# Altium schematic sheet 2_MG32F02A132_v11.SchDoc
size 381 x 241 mm
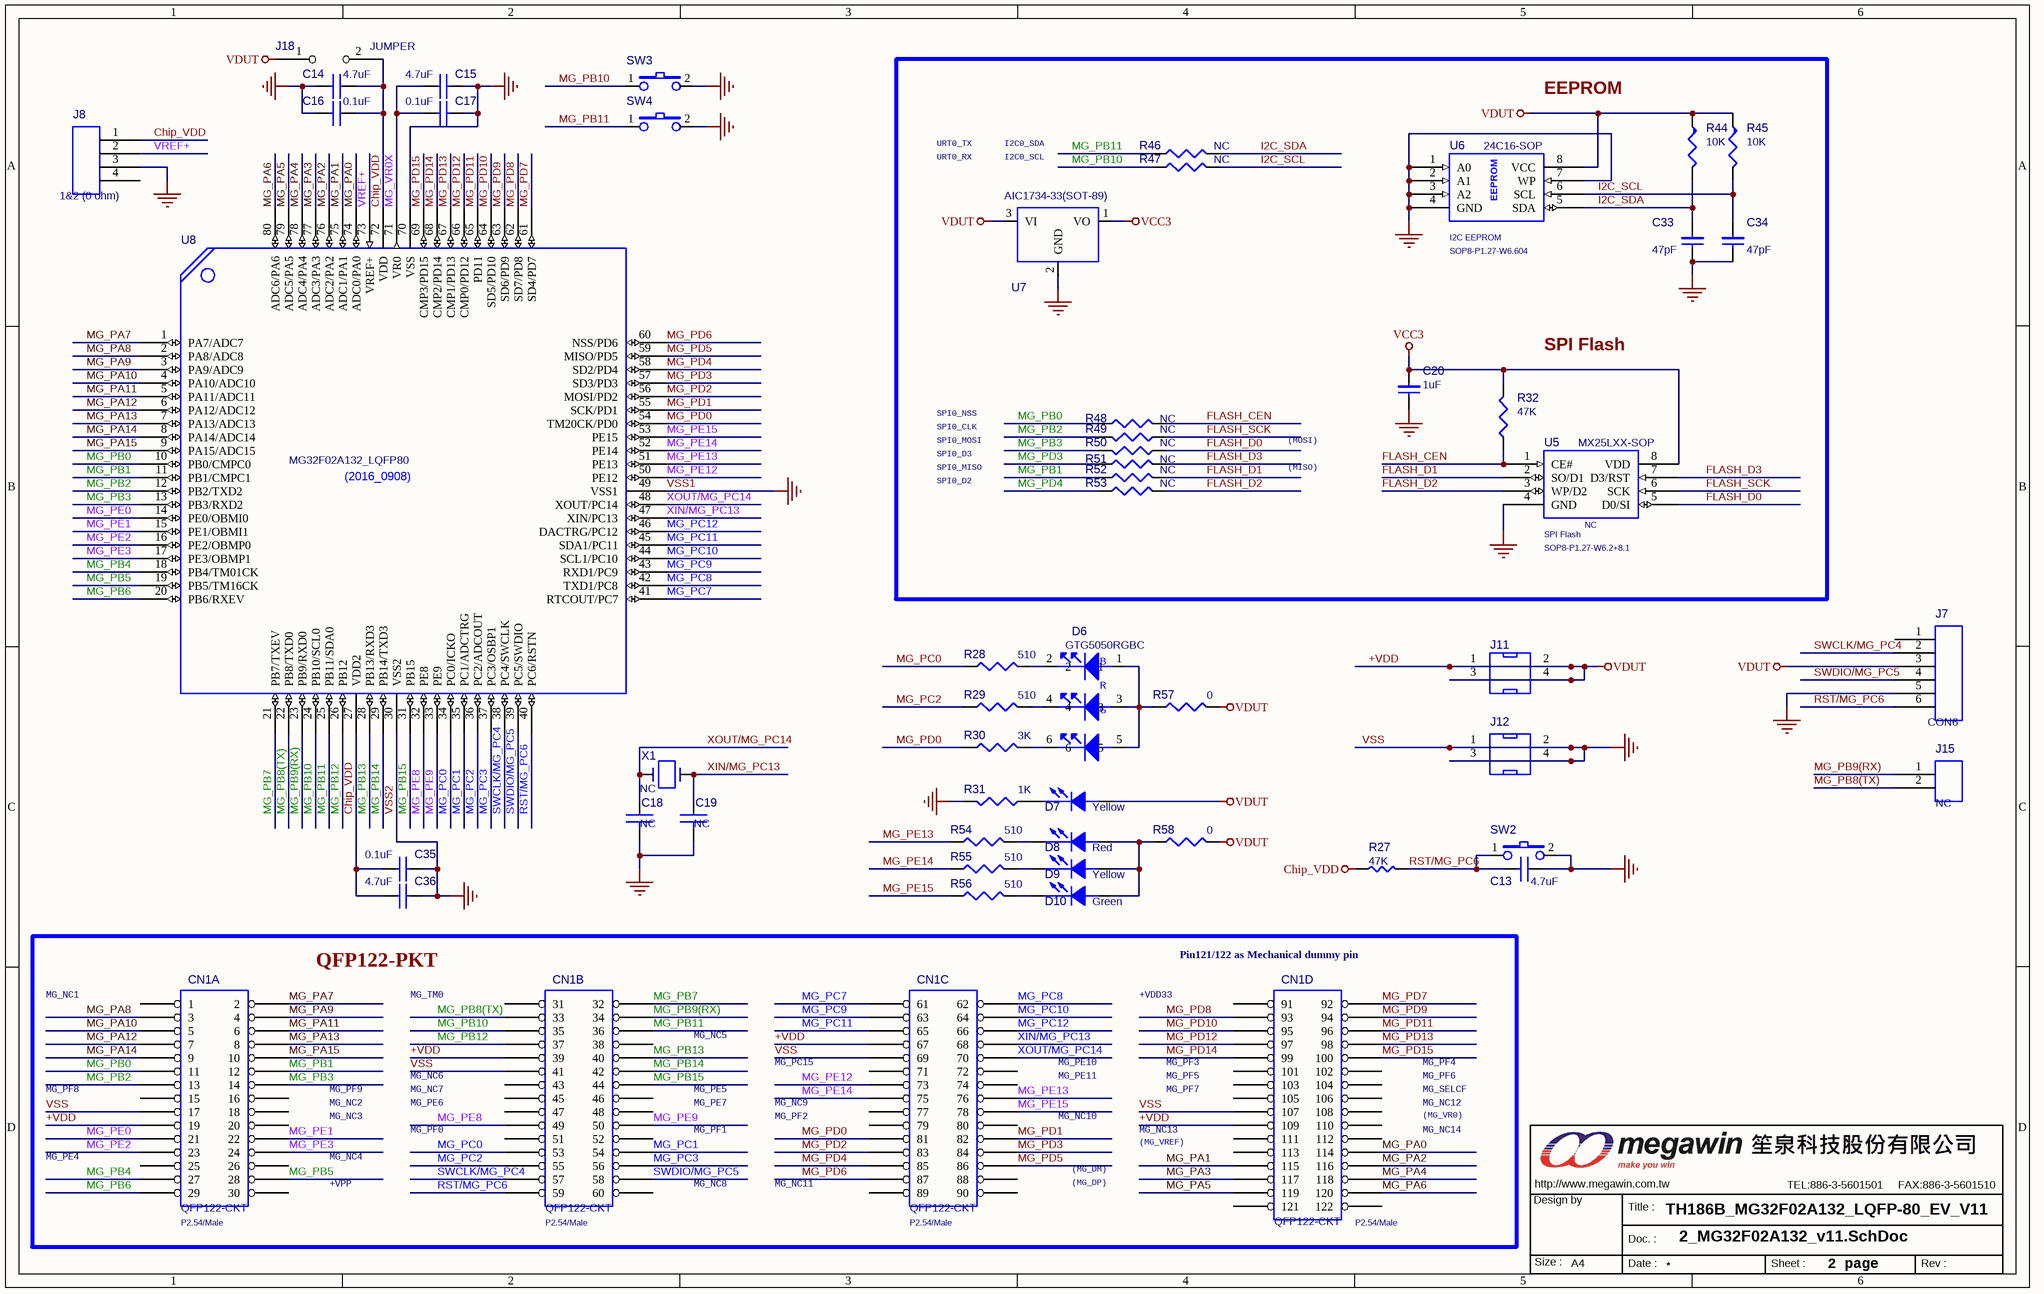
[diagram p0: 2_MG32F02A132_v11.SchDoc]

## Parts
C13  4.7uF  [0805C]
C14  4.7uF  [0805C]
C15  4.7uF  [0805C]
C16  0.1uF  [0603C]
C17  0.1uF  [0603C]
C18  NC  [0603C]
C19  NC  [0603C]
C20  1uF  [0603C]
C33  47pF  [0603C]
C34  47pF  [0603C]
C35  0.1uF  [0603C]
C36  4.7uF  [0805C]
CN1  QFP122-CKT  Package: P2.54/Male  [QFP122-P2.54-CKT]  (parts A,B,C,D of 4)
D6  GTG5050RGBC
D7  Yellow  [0805D]
D8  Red  [LED38+0805]
D9  Yellow  [LED38+0805]
D10  Green  [LED38+0805]
J7  CON6  [PS6P254]
J8  1&2 (0 ohm)  [PS4P254]
J11  CONN SOCKET 2x2/SM  [PS2X2P254]  (value not drawn)
J12  CONN SOCKET 2x2/SM  [PS2X2P254]  (value not drawn)
J15  NC  [PS2P254]
J18  JUMPER
MW1  OrgAddr3: TEL:886-3-5601501     FAX:886-3-5601510  [MEGAWIN_3.4]  (hidden comment: MW-A4)  (graphical)
R27  47K  [0603R]
R28  510  [0603R]
R29  510  [0603R]
R30  3K  [0603R]
R31  1K  [0603R]
R32  47K  [0603R]
R44  10K  [0603R]
R45  10K  [0603R]
R46  NC  [PS2p254+0603]
R47  NC  [PS2p254+0603]
R48  NC  [PS2p254+0603]
R49  NC  [PS2p254+0603]
R50  NC  [PS2p254+0603]
R51  NC  [PS2p254+0603]
R52  NC  [PS2p254+0603]
R53  NC  [PS2p254+0603]
R54  510  [0603R]
R55  510  [0603R]
R56  510  [0603R]
R57  0  [PS2p254+0603]
R58  0  [PS2p254+0603]
SW2  SW TACT-SPST  (value not drawn)
SW3  SW TACT-SPST  (value not drawn)
SW4  SW TACT-SPST  (value not drawn)
U5  MX25LXX-SOP  Package: SOP8-P1.27-W6.2+8.1  Assembly: NC  Function: SPI Flash  [SO8_208P127]
U6  24C16-SOP  Package: SOP8-P1.27-W6.604  Function: I2C EEPROM  [SO8_150P127]
U7  AIC1734-33(SOT-89)  [SOT89]
U8  MG32F02A132_LQFP80  [QFP80-P0.4-Z12X12]
X1  NC  [X49U]

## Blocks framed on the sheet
QFP122-PKT: CN1

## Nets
+VDD: CN1.19 CN1.39 CN1.67 CN1.109 D7.1(ANODE) J7.3 J11.1 J11.2 J11.3 J11.4 J18.1 R44.1 R45.1 R57.2 R58.2 U6.8(VCC) U7.3(VI)  [also labelled VDUT]
Chip_VDD: C14.1 C16.1 C35.1 C36.1 J8.1 J18.2 R27.1 U8.27(VDD2) U8.72(VDD)
VCC3: C20.1 R32.2 U5.8(VDD) U7.1(VO)
VSS: C13.1 C14.2 C15.2 C16.2 C17.2 C18.2 C19.2 C20.2 C33.2 C34.2 C35.2 C36.2 CN1.17 CN1.41 CN1.69 CN1.107 J7.5 J8.3 J12.1 J12.2 J12.3 J12.4 R31.1 SW2.2 SW3.2 SW4.2 U5.4(GND) U6.1(A0) U6.2(A1) U6.3(A2) U6.4(GND) U6.7(WP) U7.2(GND) U8.30(VSS2) U8.49(VSS1) U8.70(VSS)  [also labelled GND_POWER, VSS1, VSS2]
FLASH_CEN: R32.1 R48.2 U5.1(CE#)
FLASH_D0: R50.1 U5.5(D0/SI)
FLASH_D1: R52.2 U5.2(SO/D1)
FLASH_D2: R53.2 U5.3(WP/D2)
FLASH_D3: R51.2 U5.7(D3/RST)
FLASH_SCK: R49.1 U5.6(SCK)
I2C_SCL: C34.1 R45.2 R47.2 U6.6(SCL)
I2C_SDA: C33.1 R44.2 R46.2 U6.5(SDA)
MG_PA0: CN1.114 U8.74(ADC0/PA0)
MG_PA1: CN1.115 U8.75(ADC1/PA1)
MG_PA2: CN1.116 U8.76(ADC2/PA2)
MG_PA3: CN1.117 U8.77(ADC3/PA3)
MG_PA4: CN1.118 U8.78(ADC4/PA4)
MG_PA5: CN1.119 U8.79(ADC5/PA5)
MG_PA6: CN1.120 U8.80(ADC6/PA6)
MG_PA7: CN1.2 U8.1(PA7/ADC7)
MG_PA8: CN1.3 U8.2(PA8/ADC8)
MG_PA9: CN1.4 U8.3(PA9/ADC9)
MG_PA10: CN1.5 U8.4(PA10/ADC10)
MG_PA11: CN1.6 U8.5(PA11/ADC11)
MG_PA12: CN1.7 U8.6(PA12/ADC12)
MG_PA13: CN1.8 U8.7(PA13/ADC13)
MG_PA14: CN1.9 U8.8(PA14/ADC14)
MG_PA15: CN1.10 U8.9(PA15/ADC15)
MG_PB0: CN1.11 R48.1 U8.10(PB0/CMPC0)
MG_PB1: CN1.12 R52.1 U8.11(PB1/CMPC1)
MG_PB2: CN1.13 R49.2 U8.12(PB2/TXD2)
MG_PB3: CN1.14 R50.2 U8.13(PB3/RXD2)
MG_PB4: CN1.27 U8.18(PB4/TM01CK)
MG_PB5: CN1.28 U8.19(PB5/TM16CK)
MG_PB6: CN1.29 U8.20(PB6/RXEV)
MG_PB7: CN1.32 U8.21(PB7/TXEV)
MG_PB8(TX): CN1.33 J15.2 U8.22(PB8/TXD0)
MG_PB9(RX): CN1.34 J15.1 U8.23(PB9/RXD0)
MG_PB10: CN1.35 R47.1 SW3.1 U8.24(PB10/SCL0)
MG_PB11: CN1.36 R46.1 SW4.1 U8.25(PB11/SDA0)
MG_PB12: CN1.37 U8.26(PB12)
MG_PB13: CN1.40 U8.28(PB13/RXD3)
MG_PB14: CN1.42 U8.29(PB14/TXD3)
MG_PB15: CN1.44 U8.31(PB15)
MG_PC0: CN1.53 R28.1 U8.34(PC0/ICKO)
MG_PC1: CN1.54 U8.35(PC1/ADCTRG)
MG_PC2: CN1.55 R29.1 U8.36(PC2/ADCOUT)
MG_PC3: CN1.56 U8.37(PC3/OSBP1)
MG_PC7: CN1.61 U8.41(RTCOUT/PC7)
MG_PC8: CN1.62 U8.42(TXD1/PC8)
MG_PC9: CN1.63 U8.43(RXD1/PC9)
MG_PC10: CN1.64 U8.44(SCL1/PC10)
MG_PC11: CN1.65 U8.45(SDA1/PC11)
MG_PC12: CN1.66 U8.46(DACTRG/PC12)
MG_PD0: CN1.81 R30.1 U8.54(TM20CK/PD0)
MG_PD1: CN1.82 U8.55(SCK/PD1)
MG_PD2: CN1.83 U8.56(MOSI/PD2)
MG_PD3: CN1.84 R51.1 U8.57(SD3/PD3)
MG_PD4: CN1.85 R53.1 U8.58(SD2/PD4)
MG_PD5: CN1.86 U8.59(MISO/PD5)
MG_PD6: CN1.87 U8.60(NSS/PD6)
MG_PD7: CN1.92 U8.61(SD4/PD7)
MG_PD8: CN1.93 U8.62(SD7/PD8)
MG_PD9: CN1.94 U8.63(SD6/PD9)
MG_PD10: CN1.95 U8.64(SD5/PD10)
MG_PD11: CN1.96 U8.65(PD11)
MG_PD12: CN1.97 U8.66(CMP0/PD12)
MG_PD13: CN1.98 U8.67(CMP1/PD13)
MG_PD14: CN1.99 U8.68(CMP2/PD14)
MG_PD15: CN1.100 U8.69(CMP3/PD15)
MG_PE0: CN1.21 U8.14(PE0/OBMI0)
MG_PE1: CN1.22 U8.15(PE1/OBMI1)
MG_PE2: CN1.23 U8.16(PE2/OBMP0)
MG_PE3: CN1.24 U8.17(PE3/OBMP1)
MG_PE8: CN1.49 U8.32(PE8)
MG_PE9: CN1.50 U8.33(PE9)
MG_PE12: CN1.73 U8.50(PE12)
MG_PE13: CN1.76 R54.1 U8.51(PE13)
MG_PE14: CN1.75 R55.1 U8.52(PE14)
MG_PE15: CN1.78 R56.1 U8.53(PE15)
MG_VR0X: C15.1 C17.1 U8.71(VR0)
RST/MG_PC6: C13.2 CN1.59 J7.6 R27.2 SW2.1 U8.40(PC6/RSTN)
SWCLK/MG_PC4: CN1.57 J7.2 U8.38(PC4/SWCLK)
SWDIO/MG_PC5: CN1.58 J7.4 U8.39(PC5/SWDIO)
VREF+: J8.2 U8.73(VREF+)
XIN/MG_PC13: C19.1 CN1.68 U8.47(XIN/PC13) X1.2
XOUT/MG_PC14: C18.1 CN1.70 U8.48(XOUT/PC14) X1.1
NetD6_1: D6.1 D6.3 D6.5 R57.1
NetD6_2: D6.2 R28.2
NetD6_4: D6.4 R29.2
NetD6_6: D6.6 R30.2
NetD7_2: D7.2(CATHODE) R31.2
NetD8_1: D8.1(ANODE) D9.1(ANODE) D10.1(ANODE) R58.1
NetD8_2: D8.2(CATHODE) R54.2
NetD9_2: D9.2(CATHODE) R55.2
NetD10_2: D10.2(CATHODE) R56.2

Not connected (* = marked no-connect by the designer): CN1 1 15 16 18 20 25 26 30 31 38 43 45 46 47 48 51 52 60 71 72 74 77 79 80 88 89 90 91 101 102 103 104 105 106 108 110 111 112 113 121 122; J7 1; J8 4

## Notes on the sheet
- EEPROM
- URT0_TX
- URT0_RX
- I2C0_SDA
- I2C0_SCL
- SPI Flash
- SPI0_NSS
- SPI0_CLK
- SPI0_MOSI
- SPI0_MISO
- SPI0_D3
- SPI0_D2
- (MOSI)
- (MISO)
- (near CN1) Pin121/122 as Mechanical dummy pin
- MG_NC1
- MG_TM0
- MG_NC5
- +VDD33
- MG_PF8
- MG_NC2
- MG_PF9
- MG_NC6
- MG_NC7
- MG_PE6
- MG_PE5
- MG_PE7
- MG_PC15
- MG_NC9
- MG_PE10
- MG_PE11
- MG_PF3
- MG_PF5
- MG_PF7
- MG_NC12
- MG_PF4
- MG_PF6
- MG_SELCF
- MG_PE4
- MG_NC3
- MG_NC4
- MG_PF0
- MG_PF1
- MG_PF2
- MG_NC10
- (MG_DM)
- MG_NC13
- (MG_VREF)
- MG_NC14
- (MG_VR0)
- +VPP
- MG_NC8
- MG_NC11
- (MG_DP)
- TH186B_MG32F02A132_LQFP-80_EV_V11
- 2 page

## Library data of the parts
C13-C17 C35 C36 = CAP NP_Dup1
C18 C19 = C NP_Dup1
C20 C33 C34 = CAP-NP
D6 = LED_GTG5050RGBC
D7-D10 = LED
J7 = CON6_Dup1
J8 = CON4
J15 = CON2
MW1 = MW_A4_2
R27 = R_Dup4
R28-R32 R46-R58 = R_Dup5
R44 R45 = R: 2ND PART FIELD: SMD_0805
U5 = ICM-25LXX
U6 = ICM-24CXX: 2ND PART FIELD: SOP_8PIN; 1ST PART FIELD: OSD Record Buffer
U7 = AIC1722-33
U8 = IC-FA217-LQFP80: SPLIT_INST: TRUE; SWAP_INFO: (S1+S2); OriginalSymbolOrigin: (0,0); Designator: A
X1 = CRYSTAL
